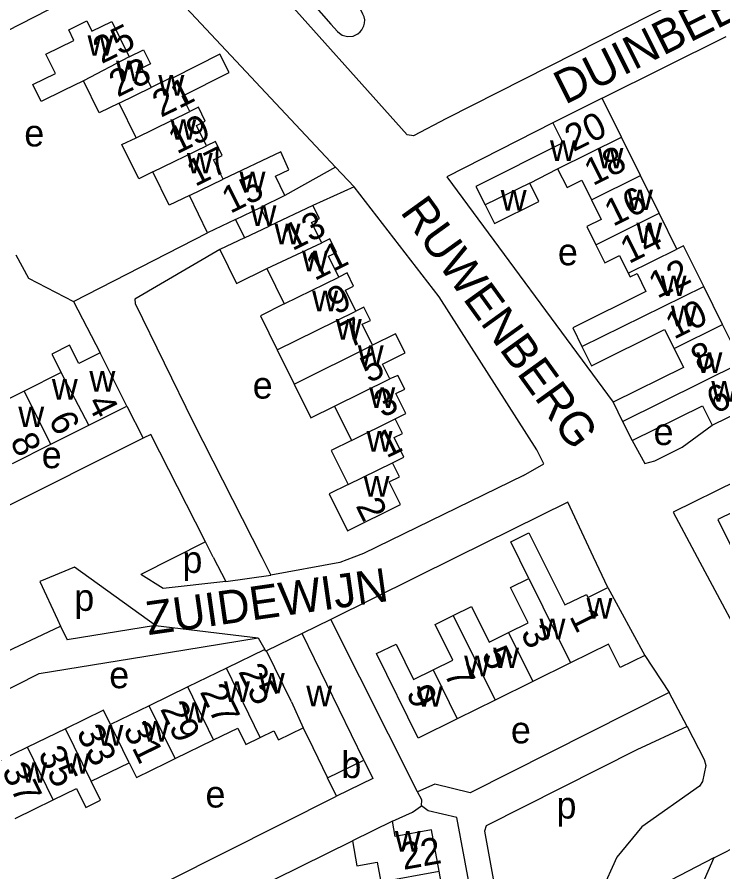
# Model space of a CAD drawing. Extents: x 157794 to 159375, y 380877 to 382306.
# Drawn here: x 158682.4 to 158787.7, y 381703 to 381830.6 of the extents above; entities that cross this region are included whole.
import ezdxf

# ---------------------------------------------------------------- set-up
doc = ezdxf.new("R2010")
doc.units = 0
for name, color, linetype in [('BLT_Basislijn', 7, 'Continuous'), ('BLT_Bebouwing', 7, 'Continuous'), ('BLT_Centroide', 7, 'Continuous'), ('BLT_Huisnummer', 7, 'Continuous'), ('BLT_Huisnummer_ tussenligend', 7, 'Continuous'), ('BLT_Onderdoorgang_en_onderverdeling', 7, 'Continuous'), ('BLT_Onderverdeling_panden', 7, 'Continuous'), ('BLT_Straatnaam', 7, 'Continuous')]:
    doc.layers.add(name, color=color, linetype=linetype)

msp = doc.modelspace()

# ---------------------------------------------------------------- linework, layer by layer
at = {"layer": 'BLT_Basislijn'}
for p, q in [((158769.67, 381818.51), (158788.19, 381827.72)), ((158762.32, 381814.86), (158746.52, 381806.8)), ((158729.92, 381808.22), (158722.35, 381803.99)), ((158729.92, 381808.22), (158732.7, 381805.28)), ((158746.52, 381806.8), (158771.31, 381773.12)), ((158732.7, 381805.28), (158726.54, 381802.52)), ((158690.84, 381788.15), (158710.82, 381798.41)), ((158690.84, 381788.15), (158694.81, 381780.48)), ((158698.78, 381772.54), (158701.22, 381767.75)), ((158781.62, 381766.42), (158786.07, 381769.7)), ((158701.22, 381767.75), (158667.12, 381750.72)), ((158764.57, 381758.23), (158747.95, 381750)), ((158768.39, 381750), (158764.57, 381758.23)), ((158780.24, 381756.7), (158783.83, 381750)), ((158710.51, 381752.28), (158709.02, 381755.21)), ((158710.51, 381752.28), (158700.88, 381747.43)), ((158711.67, 381750), (158710.51, 381752.28)), ((158711.67, 381750), (158713.52, 381746.38)), ((158718.89, 381750), (158720.25, 381747.3)), ((158747.95, 381750), (158729.21, 381740.71)), ((158770.5, 381745.46), (158768.39, 381750)), ((158713.52, 381746.38), (158720.25, 381747.3)), ((158688.44, 381740.69), (158688.9, 381739.7)), ((158688.9, 381739.7), (158689.86, 381737.65)), ((158703.07, 381739.8), (158689.86, 381737.65)), ((158703.07, 381739.8), (158718.36, 381737.96)), ((158729.21, 381740.71), (158724.94, 381738.6)), ((158742.15, 381714.96), (158729.21, 381740.71)), ((158776.02, 381735.35), (158779.67, 381729.8)), ((158782.36, 381724.73), (158779.67, 381729.8)), ((158716.99, 381700.06), (158732.42, 381707.65)), ((158786.33, 381705.11), (158791.54, 381707.79))]:
    msp.add_line(p, q, dxfattribs=at)
for points in [[(158822.4, 381875.45), (158830.44, 381858.83), (158830.5, 381858.1), (158746.44, 381815.46)], [(158668.66, 381822.29), (158693.17, 381834.91), (158697.67, 381835.98), (158700.11, 381835.95), (158703.19, 381835.33), (158706.15, 381833.64), (158729.92, 381808.22)], [(158746.44, 381815.46), (158741.55, 381812.91), (158740.58, 381813.02), (158719.85, 381836.26)], [(158757.94, 381762.18), (158760.95, 381763.95), (158759.93, 381766.01), (158745.35, 381788.86), (158732.7, 381805.28)], [(158712.64, 381795.92), (158699.95, 381788.52), (158700.02, 381787.85), (158708.69, 381770.17), (158718.89, 381750)], [(158682.24, 381795.11), (158684.1, 381791.64), (158690.84, 381788.15)], [(158709.02, 381755.21), (158702.37, 381768.32), (158701.22, 381767.75)], [(158774.14, 381767.41), (158776.06, 381763.99), (158777.54, 381764.38), (158781.62, 381766.42)], [(158757.94, 381762.18), (158734.06, 381750.53), (158732.64, 381750)], [(158789.74, 381761.4), (158780.24, 381756.7)], [(158732.64, 381750), (158730.56, 381749.22), (158720.25, 381747.3)], [(158783.83, 381750), (158792.83, 381733.2), (158796.01, 381728.22), (158798.96, 381728.74), (158803.4, 381731.45)], [(158703.07, 381739.8), (158690.97, 381748.5), (158685.78, 381746.39)], [(158713.52, 381746.38), (158704.18, 381745.34), (158700.88, 381747.43)], [(158685.78, 381746.39), (158688.44, 381740.69)], [(158669.46, 381730.54), (158688.9, 381739.7)], [(158707.42, 381736.18), (158718.36, 381737.96)], [(158718.36, 381737.96), (158719.37, 381736.24)], [(158675.27, 381727.38), (158685.69, 381732.64), (158707.42, 381736.18)], [(158779.67, 381729.8), (158749.97, 381714.84), (158744.72, 381716.13), (158742.15, 381714.96)], [(158782.36, 381724.73), (158774.85, 381721.25), (158752.36, 381709.92), (158752.12, 381709.08), (158757.99, 381676.79), (158759.2, 381671.63), (158759.99, 381670.45), (158763.24, 381668.05)], [(158782.36, 381724.73), (158784.91, 381719.82), (158785.13, 381718.93), (158784.65, 381716.54), (158784.18, 381715.81), (158775.58, 381709.73), (158771.84, 381705.21), (158769.52, 381700.05), (158768.24, 381694.81), (158766.51, 381693.47), (158763.24, 381668.05)], [(158676.42, 381708.23), (158685.06, 381690.53), (158685.76, 381690.61), (158704.31, 381699.68), (158704.78, 381699.99), (158704.62, 381701.43), (158705.04, 381701.74), (158730.07, 381714.32)], [(158742.71, 381712.87), (158742.8, 381713.8), (158742.15, 381714.96)], [(158738.39, 381710.58), (158741.4, 381711.94), (158742.71, 381712.87)], [(158756.8, 381663.95), (158747.99, 381711.13), (158743.71, 381712.16), (158742.71, 381712.87)], [(158786.33, 381705.11), (158779.92, 381701.77), (158776.5, 381680.83), (158774.74, 381667.82)], [(158786.33, 381705.11), (158783.62, 381699.01), (158783.7, 381697.35), (158785.32, 381688.89), (158784.97, 381687.97), (158783.38, 381686.09), (158784.33, 381679.41), (158781.07, 381678.63), (158780.85, 381678.09), (158782.09, 381669.18), (158781.86, 381668.93), (158774.74, 381667.82)]]:
    msp.add_lwpolyline(points, dxfattribs=at)
at = {"layer": 'BLT_Bebouwing'}
for p, q in [((158700.17, 381812.62), (158697.65, 381817.79)), ((158769.67, 381818.51), (158762.32, 381814.86)), ((158772.55, 381812.7), (158769.67, 381818.51)), ((158775.39, 381806.98), (158772.55, 381812.7)), ((158778.18, 381801.34), (158775.39, 381806.98)), ((158710.82, 381798.41), (158708.1, 381804)), ((158718.69, 381802.21), (158720.03, 381799.43)), ((158726.54, 381802.52), (158720.03, 381799.43)), ((158780.83, 381795.99), (158778.18, 381801.34)), ((158715, 381800.42), (158716.33, 381797.67)), ((158716.33, 381797.67), (158712.64, 381795.92)), ((158719.64, 381793.09), (158722.24, 381787.8)), ((158787.63, 381784.73), (158784.83, 381790.39)), ((158790.44, 381779.05), (158787.63, 381784.73)), ((158698.78, 381772.54), (158694.81, 381780.48)), ((158721.22, 381780.96), (158723.74, 381775.85)), ((158683.45, 381774.8), (158677.77, 381771.95)), ((158771.31, 381773.12), (158772.72, 381770.27)), ((158786.07, 381769.7), (158793.3, 381773.28)), ((158693.1, 381769.7), (158698.78, 381772.54)), ((158729.77, 381772.54), (158732.29, 381767.44)), ((158772.72, 381770.27), (158774.14, 381767.41)), ((158687.42, 381766.85), (158693.1, 381769.7)), ((158681.74, 381764.01), (158687.42, 381766.85)), ((158770.5, 381745.46), (158776.02, 381735.35)), ((158724.94, 381738.6), (158719.61, 381736)), ((158734.15, 381719.72), (158724.94, 381738.6)), ((158719.37, 381736.24), (158713.62, 381733.44)), ((158713.62, 381733.44), (158707.87, 381730.63)), ((158764.95, 381734.21), (158759.32, 381731.44)), ((158707.87, 381730.63), (158702.12, 381727.82)), ((158759.32, 381731.44), (158753.7, 381728.67)), ((158753.7, 381728.67), (158748.06, 381725.89)), ((158702.12, 381727.82), (158696.36, 381725.02)), ((158689.63, 381724.4), (158683.95, 381721.63)), ((158705.97, 381719.93), (158711.72, 381722.74)), ((158683.95, 381721.63), (158678.27, 381718.86)), ((158693.46, 381716.55), (158699.14, 381719.32)), ((158730.07, 381714.32), (158728.73, 381717.07)), ((158682.1, 381711), (158687.78, 381713.78)), ((158738.39, 381710.58), (158732.42, 381707.65)), ((158746.46, 381696.9), (158745.34, 381703.11))]:
    msp.add_line(p, q, dxfattribs=at)
for points in [[(158733.02, 381842.02), (158727.88, 381839.44), (158726.11, 381841.43), (158722, 381837.8), (158729.22, 381829.58), (158730.2, 381828.46), (158730.49, 381828.21), (158730.91, 381827.92), (158731.7, 381827.72), (158732.52, 381827.78), (158733.22, 381828.13), (158733.6, 381828.44), (158733.83, 381828.74), (158734.12, 381829.3), (158734.21, 381829.73), (158734.25, 381830.19), (158734.17, 381830.68), (158734, 381831.06), (158733.38, 381832.3), (158736.99, 381834.12)], [(158692.33, 381821.11), (158689.35, 381819.66), (158685.99, 381818.03), (158684.77, 381820.55), (158688.12, 381822.18), (158686.69, 381825.11), (158690.87, 381827.15), (158690.11, 381828.73), (158692.81, 381830.05), (158693.56, 381828.52), (158696.52, 381829.96), (158699.1, 381824.69)], [(158699.1, 381824.69), (158701.27, 381825.75), (158702.3, 381823.64), (158701.02, 381823.01), (158702.43, 381820.12)], [(158707.04, 381818.83), (158714.06, 381822.33), (158712.67, 381825.11), (158705.71, 381821.54), (158705.64, 381821.69), (158702.43, 381820.12)], [(158697.65, 381817.79), (158694.66, 381816.34), (158692.33, 381821.11)], [(158708.17, 381816.52), (158707.04, 381818.83)], [(158710.67, 381811.4), (158709.18, 381814.44), (158710.47, 381815.07), (158709.46, 381817.15), (158708.17, 381816.52)], [(158762.32, 381814.86), (158763.8, 381811.87), (158750.85, 381805.35), (158752.21, 381802.59)], [(158702.66, 381807.5), (158700.55, 381806.47), (158698.05, 381811.59), (158700.17, 381812.62)], [(158713.12, 381806.44), (158711.72, 381809.31), (158713, 381809.94), (158711.98, 381812.04), (158710.67, 381811.4)], [(158722.35, 381803.99), (158720.96, 381806.86), (158722.94, 381807.82), (158721.76, 381810.5), (158713.12, 381806.44)], [(158708.1, 381804), (158705.08, 381802.53), (158702.66, 381807.5)], [(158758.87, 381805.81), (158763.03, 381807.99)], [(158763.03, 381807.99), (158764.43, 381805.18), (158766.63, 381806.27), (158768.07, 381803.35)], [(158752.21, 381802.59), (158753.6, 381799.79), (158760.22, 381803.07), (158758.87, 381805.81)], [(158722.35, 381803.99), (158718.69, 381802.21)], [(158768.07, 381803.35), (158769.52, 381800.43), (158767.37, 381799.37), (158768.71, 381796.65)], [(158727.84, 381796.92), (158726.33, 381799.98), (158727.5, 381800.56), (158726.54, 381802.52)], [(158715, 381800.42), (158710.82, 381798.41)], [(158730.4, 381791.82), (158728.87, 381794.91), (158730.05, 381795.49), (158729.05, 381797.52), (158727.84, 381796.92)], [(158712.64, 381795.92), (158715.14, 381790.87), (158719.64, 381793.09)], [(158768.71, 381796.65), (158770.06, 381793.94), (158772.24, 381795.02), (158773.55, 381792.38)], [(158784.83, 381790.39), (158781.81, 381796.47), (158780.83, 381795.99)], [(158732.93, 381786.74), (158731.38, 381789.88), (158732.6, 381790.47), (158731.63, 381792.43), (158730.4, 381791.82)], [(158773.55, 381792.38), (158773.83, 381791.83), (158774.87, 381792.34), (158776.21, 381789.64), (158765.28, 381784.24), (158766.65, 381781.47)], [(158722.24, 381787.8), (158718.71, 381786.05), (158721.22, 381780.96)], [(158735.42, 381781.66), (158733.9, 381784.76), (158735.1, 381785.35), (158734.12, 381787.33), (158732.93, 381786.74)], [(158737.99, 381776.6), (158736.9, 381778.81), (158740.28, 381780.48), (158738.86, 381783.36), (158735.42, 381781.66)], [(158766.65, 381781.47), (158768.1, 381778.55), (158778.99, 381783.98), (158780.4, 381781.15)], [(158694.81, 381780.48), (158691.62, 381778.89), (158690.24, 381781.65), (158687.6, 381780.33), (158688.98, 381777.59)], [(158780.4, 381781.15), (158781.8, 381778.32), (158771.31, 381773.12)], [(158688.98, 381777.59), (158683.45, 381774.8)], [(158738.8, 381770.65), (158740.39, 381771.43), (158738.91, 381774.43), (158740.22, 381775.07), (158739.21, 381777.12), (158737.99, 381776.6)], [(158723.74, 381775.85), (158726.23, 381770.79), (158729.77, 381772.54)], [(158774.14, 381767.41), (158784.63, 381772.61), (158786.07, 381769.7)], [(158738.39, 381764.1), (158740.1, 381764.94), (158738.66, 381767.85), (158739.88, 381768.45), (158738.8, 381770.65)], [(158732.29, 381767.44), (158729.26, 381765.94), (158731.78, 381760.84)], [(158731.78, 381760.84), (158728.96, 381759.45), (158731.68, 381753.94), (158739.6, 381757.85), (158737.92, 381761.24), (158739.44, 381761.99), (158738.39, 381764.1)], [(158789.74, 381761.4), (158791.52, 381757.88), (158786.93, 381755.65), (158789.73, 381750)], [(158758.73, 381746.82), (158756.04, 381752.29), (158758.74, 381753.62), (158761.45, 381748.16), (158764.11, 381742.87), (158767.32, 381744.45), (158767.54, 381744), (158770.5, 381745.46)], [(158755.72, 381738.75), (158758.62, 381740.18), (158756.01, 381745.47), (158758.73, 381746.82)], [(158747.47, 381741.3), (158750.2, 381742.65), (158752.82, 381737.32), (158755.72, 381738.75)], [(158744.47, 381733.17), (158747.39, 381734.61), (158744.75, 381739.96), (158747.47, 381741.3)], [(158748.06, 381725.89), (158742.21, 381723.01), (158736.01, 381735.6), (158738.93, 381737.04), (158741.55, 381731.74), (158744.47, 381733.17)], [(158776.02, 381735.35), (158772.35, 381733.55), (158770.64, 381737.02), (158764.95, 381734.21)], [(158719.61, 381736), (158719.52, 381735.95), (158719.37, 381736.24)], [(158696.36, 381725.02), (158695.31, 381727.17), (158689.63, 381724.4)], [(158711.72, 381722.74), (158715.33, 381724.5), (158716.53, 381722.05), (158718.67, 381723.1)], [(158718.67, 381723.1), (158720.72, 381724.1), (158721.4, 381722.72), (158725.09, 381724.52)], [(158725.09, 381724.52), (158726.54, 381721.57), (158728.73, 381717.07)], [(158699.14, 381719.32), (158700.22, 381717.12), (158704.71, 381719.31), (158705.97, 381719.93)], [(158734.15, 381719.72), (158735.49, 381716.97), (158730.07, 381714.32)], [(158687.78, 381713.78), (158691.27, 381715.47), (158692.64, 381712.65), (158694.84, 381713.73), (158693.46, 381716.55)], [(158745.34, 381703.11), (158744.21, 381709.32), (158738.8, 381708.33), (158738.39, 381710.58)], [(158732.42, 381707.65), (158733.1, 381703.91), (158736.13, 381704.46), (158736.66, 381701.53)]]:
    msp.add_lwpolyline(points, dxfattribs=at)
at = {"layer": 'BLT_Onderdoorgang_en_onderverdeling'}
msp.add_line((158716.33, 381797.67), (158720.03, 381799.43), dxfattribs=at)
at = {"layer": 'BLT_Onderverdeling_panden'}
for p, q in [((158699.1, 381824.69), (158692.33, 381821.11)), ((158697.65, 381817.79), (158702.43, 381820.12)), ((158700.17, 381812.62), (158708.17, 381816.52)), ((158763.03, 381807.99), (158772.55, 381812.7)), ((158702.66, 381807.5), (158710.67, 381811.4)), ((158708.1, 381804), (158713.12, 381806.44)), ((158768.07, 381803.35), (158775.39, 381806.98)), ((158758.87, 381805.81), (158752.21, 381802.59)), ((158715, 381800.42), (158718.69, 381802.21)), ((158768.71, 381796.65), (158778.18, 381801.34)), ((158773.55, 381792.38), (158780.83, 381795.99)), ((158722.24, 381787.8), (158730.4, 381791.82)), ((158766.65, 381781.47), (158784.83, 381790.39)), ((158721.22, 381780.96), (158732.93, 381786.74)), ((158780.4, 381781.15), (158787.63, 381784.73)), ((158723.74, 381775.85), (158735.42, 381781.66)), ((158772.72, 381770.27), (158790.44, 381779.05)), ((158693.1, 381769.7), (158688.98, 381777.59)), ((158729.77, 381772.54), (158737.99, 381776.6)), ((158687.42, 381766.85), (158683.45, 381774.8)), ((158732.29, 381767.44), (158738.8, 381770.65)), ((158731.78, 381760.84), (158738.39, 381764.1)), ((158758.73, 381746.82), (158764.95, 381734.21)), ((158747.47, 381741.3), (158753.7, 381728.67)), ((158755.72, 381738.75), (158759.32, 381731.44)), ((158723.32, 381728.4), (158719.61, 381736)), ((158718.67, 381723.1), (158713.62, 381733.44)), ((158744.47, 381733.17), (158748.06, 381725.89)), ((158711.72, 381722.74), (158707.87, 381730.63)), ((158723.32, 381728.4), (158725.09, 381724.52)), ((158705.97, 381719.93), (158702.12, 381727.82)), ((158693.46, 381716.55), (158689.63, 381724.4)), ((158699.14, 381719.32), (158696.36, 381725.02)), ((158687.78, 381713.78), (158683.95, 381721.63)), ((158728.73, 381717.07), (158734.15, 381719.72)), ((158736.66, 381701.53), (158745.34, 381703.11))]:
    msp.add_line(p, q, dxfattribs=at)
msp.add_lwpolyline([(158719.64, 381793.09), (158727.84, 381796.92)], dxfattribs=at)

# ---------------------------------------------------------------- texts
at = {"layer": 'BLT_Centroide'}
for s, p in [('w', (158692.91, 381824.84)), ('w', (158697.17, 381821.03)), ('w', (158703.48, 381818.88)), ('w', (158705.27, 381812.31)), ('e', (158683.48, 381811.31)), ('w', (158761.89, 381809.16)), ('w', (158768.98, 381808.03)), ('w', (158707.73, 381807.28)), ('w', (158715.59, 381804.47)), ('w', (158754.54, 381801.73)), ('w', (158773.38, 381801.81)), ('w', (158717.23, 381799.45)), ('w', (158720.81, 381796.69)), ('w', (158774.77, 381796.88)), ('w', (158724.91, 381792.66)), ('e', (158763.07, 381793.57)), ('w', (158778.4, 381788.97)), ('w', (158726.42, 381786.69)), ('w', (158779.92, 381784.47)), ('w', (158729.95, 381782.47)), ('w', (158733.22, 381778.56)), ('w', (158783.73, 381777.5)), ('w', (158687.59, 381773.53)), ('w', (158693.19, 381774.7)), ('e', (158717.55, 381773.67)), ('w', (158734.94, 381772.28)), ('w', (158785.95, 381773.22)), ('w', (158682.59, 381769.41)), ('e', (158777.34, 381766.74)), ('w', (158734.53, 381765.75)), ('e', (158686.08, 381763.28)), ('w', (158734.09, 381759.03)), ('p', (158707.07, 381747.65)), ('p', (158690.94, 381741.99)), ('w', (158767.34, 381740.84)), ('w', (158760.33, 381737.75)), ('w', (158753.41, 381733.44)), ('w', (158749.09, 381732.22)), ('e', (158696.15, 381730.44)), ('w', (158718.47, 381729.66)), ('w', (158713.27, 381728.39)), ('w', (158725.54, 381727.75)), ('w', (158742.03, 381727.67)), ('w', (158706.92, 381725.28)), ('w', (158701.17, 381722.47)), ('w', (158694.39, 381721.86)), ('e', (158756.06, 381722.21)), ('w', (158689.39, 381717.67)), ('b', (158730.78, 381717.03)), ('w', (158683.03, 381716.33)), ('e', (158710.51, 381712.63)), ('p', (158762.86, 381710.99)), ('w', (158738.75, 381706.06))]:
    msp.add_text(s, height=4, dxfattribs=at).set_placement(p)
at = {"layer": 'BLT_Huisnummer'}
for s, rotation, p in [('25', 26.2594, (158695.01, 381823.58)), ('20', 26.3587, (158765.37, 381810.46)), ('19', 26.2594, (158706.24, 381810.11)), ('15', 26.2594, (158714.21, 381801.23)), ('13', 26.2594, (158723.46, 381795.67)), ('14', 26.3587, (158773.66, 381793.74)), ('9', 26.2594, (158729.94, 381786.12)), ('10', 26.3587, (158780.4, 381782.45)), ('5', 26.2594, (158734.88, 381775.93)), ('6', 26.3587, (158786.54, 381771.3)), ('4', 296.5679, (158692.76, 381773.1)), ('1', 26.2594, (158737.5, 381764.71)), ('8', 296.5679, (158681.29, 381767.35)), ('2', 296.2648, (158732.85, 381757.69)), ('1', 296.2442, (158764.72, 381741.17)), ('5', 296.2442, (158751.6, 381735.5)), ('25', 296.0165, (158715.34, 381732.94)), ('9', 296.2442, (158740.37, 381729.76)), ('29', 296.0165, (158703.69, 381727.36)), ('33', 296.0165, (158691.2, 381723.84)), ('22', 10.2955, (158740.04, 381703.31))]:
    msp.add_text(s, height=4, rotation=rotation, dxfattribs=at).set_placement(p)
at = {"layer": 'BLT_Huisnummer_ tussenligend'}
for s, rotation, p in [('23', 26.2594, (158697.4, 381818.59)), ('21', 26.2594, (158703.87, 381815.58)), ('17', 26.2594, (158708.97, 381805.26)), ('18', 26.3587, (158768.28, 381805.37)), ('16', 26.3587, (158771.3, 381799.3)), ('11', 26.2594, (158726.8, 381791.21)), ('12', 26.3587, (158777.89, 381788.53)), ('7', 26.2594, (158732, 381781.15)), ('8', 26.3587, (158784.19, 381777.54)), ('3', 26.2594, (158736.93, 381770.74)), ('6', 296.5679, (158687.03, 381770.58)), ('3', 296.2442, (158757.45, 381738.71)), ('7', 296.2442, (158746.03, 381732.65)), ('27', 296.0165, (158709.61, 381729.92)), ('31', 296.0165, (158698.17, 381724.26)), ('35', 296.0165, (158685.47, 381720.64)), ('37', 296.0165, (158680.07, 381718.13))]:
    msp.add_text(s, height=4, rotation=rotation, dxfattribs=at).set_placement(p)
at = {"layer": 'BLT_Straatnaam'}
for s, rotation, p in [('DUINBEEK', 26.5304, (158764.14, 381817.51)), ('RUWENBERG', 305.8365, (158739.45, 381801.53)), ('ZUIDEWIJN', 8.0943, (158701.97, 381738.36)), ('ZUIDEWIJN', 297.0943, (158668.45, 381708.42))]:
    msp.add_text(s, height=5, rotation=rotation, dxfattribs=at).set_placement(p)

doc.saveas('drawing.dxf')
